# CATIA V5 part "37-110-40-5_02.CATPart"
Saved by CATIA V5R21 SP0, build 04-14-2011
Part number: 37-110-40-5_02
Bounding box of the stored display mesh (mm): x -31 to 5, y 0 to 10.499, z -20 to 20
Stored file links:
  C:\Users\zerma\Pictures\Stage Stomate\37-110-40-5_02.CATPart
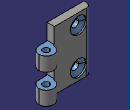
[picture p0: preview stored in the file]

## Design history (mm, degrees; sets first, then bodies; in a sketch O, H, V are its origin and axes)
AxisSystem1: origin (0, 0, 0), X (1, 0, 0), Y (0, 1, 0), Z (0, 0, 1)
Set1
  DatumCurve1 to DatumCurve3
Body1 "37-110-40-5_02" (main body)
  Solid1: solid without history
  Sketch1 on face of Solid1, origin (0, 5, 0), H (-1, 0, 0), V (0, 0, 1)
    circle A1 centre (12.5, 12.5) radius 5.25
    reference projected arc E1 centre (12.5, 12.5) radius 5.25 from (12.5, 17.75) to (12.5, 7.25) ccw from edge [face of Solid1 | face of Solid1]
    circle A2 centre (12.5, -12.5) radius 5.25
    reference projected arc E2 centre (12.5, -12.5) radius 5.25 from (12.5, -7.25) to (12.5, -17.75) ccw from edge [face of Solid1 | face of Solid1]
    coincidence: E1 A1, A2 E2
  Pad1: profile Sketch1, direction (0, -1, 0), up to face of Solid1
  Sketch2 on face of Solid1, origin (-20, 0, 0), H (0, -1, 0), V (0, 0, 1)
    line L1 (-5, 20) -> (0, 20)
    line L2 (0, 20) -> (0, -20)
    line L3 (0, -20) -> (-5, -20)
    line L4 (-5, -20) -> (-5, 20)
    reference projected line E1 (0, 20) -> (-5, 20) from edge [face of Solid1 | face of Solid1]
    reference projected line E2 (-1.6667, -20) -> (0, -20) from edge [face of Solid1 | face of Solid1]
    reference projected line E3 (0, 20) -> (0, -20) from edge [face of Solid1 | face of Solid1]
    reference projected line E4 (-5, 9.306) -> (-5, -9.306) from edge [face of Solid1 | face of Solid1]
    horizontal: L1 H, L3 H
    vertical: L2 V, L4 V
    coincidence: L1 E1, E2 L3, L2 E3, L4 E4
  Pad2: profile Sketch2, direction (-1, 0, 0), length 7, mirrored extent
  Sketch3 on face of Pad2, origin (0, 5, 0), H (-1, 0, 0), V (0, 0, 1)
    circle A1 centre (22.5, 12.4982) radius 0
    circle A2 centre (22.5, -12.5018) radius 2.5
    reference projected circle E1 centre (22.5, -12.5018) radius 2.5 from edge of DatumCurve2
    reference projected circle E2 centre (22.5, -12.5018) radius 2.5 from edge of DatumCurve2
    circle A3 centre (22.5, 12.4982) radius 2.5
    reference projected circle E3 centre (22.5, 12.4982) radius 2.5 from edge of DatumCurve3
    reference projected circle E4 centre (22.5, 12.4982) radius 2.5 from edge of DatumCurve3
    coincidence: A2 E1, E3 A3
    concentricity: A2 E2, E4 A3
  Pocket1: profile Sketch3, direction (0, -1, 0), length 7
  Pad3: profile end face of Pad2, direction along edge [face of Pad2 | face of Pad2], length 4
  Sketch4 on face of Pad3, origin (0, 5, 0), H (-1, 0, 0), V (0, 0, 1)
    circle A1 centre (22.5, 12.4982) radius 5.5
    reference projected circle E1 centre (22.5, 12.4982) radius 2.5 from edge [face of Pad2 | face of Pocket1 from Sketch3.A3]
    circle A2 centre (22.5, -12.5018) radius 5.5
    reference projected circle E2 centre (22.5, -12.5018) radius 2.5 from edge [face of Pad2 | face of Pocket1 from Sketch3.A2]
    radius A1 = 5.5
    radius A2 = 5.5
    concentricity: A1 E1, A2 E2
  Pocket2: profile Sketch4, direction (0, -1, 0), length 1
  Chamfer1: length 3, angle 26.558, on edge [end face of Pocket2 | face of Pocket1 from Sketch3.A2]
  Chamfer2: length 3, angle 26.558, on edge [end face of Pocket2 | face of Pocket1 from Sketch3.A3]
  Fillet1: radius 3.333, on edge [face of Pad3 | end face of Pad3]
  Sketch5 on face of Solid1, origin (0, 0, 10), H (1, 0, 0), V (0, 1, 0)
    line L1 (-6, 30) -> (14, 30)
    line L2 (14, 30) -> (14, 0)
    line L3 (14, 0) -> (-6, 0)
    line L4 (-6, 0) -> (-6, 30)
    reference projected line E1 (-6, 0) -> (-6, 5) from edge [face of Solid1 | face of Pad3]
    reference projected line E2 (-20, 0) -> (-6, 0) from edge [face of Pad3 | face of Pad3]
    horizontal: L1 H, L3 H
    vertical: L2 V, L4 V
    coincidence: L4 E1, L3 E2
  Pocket3: profile Sketch5, direction (0, 0, -1), length 0.5
  Sketch6 on face of Solid1, origin (0, 0, -10), H (1, 0, 0), V (0, 1, 0)
    line L1 (-6, 42.7222) -> (14, 42.7222)
    line L2 (14, 42.7222) -> (14, 0)
    line L3 (14, 0) -> (-6, 0)
    line L4 (-6, 0) -> (-6, 42.7222)
    reference projected line E1 (-6, 0) -> (-6, 5) from edge [face of Pocket3 | face of Pad3]
    reference projected line E2 (-20, 0) -> (-6, 0) from edge [face of Pad3 | face of Pad3]
    horizontal: L1 H, L3 H
    vertical: L2 V, L4 V
    coincidence: L4 E1, L3 E2
  Pocket4: profile Sketch6, direction (0, 0, -1), length 0.5
  Sketch7 on end face of Pocket3, origin (0, 0, 9.5), H (1, 0, 0), V (0, 1, 0)
    circle A1 centre (0, 5.5) radius 2.2
    reference projected arc E1 centre (0, 5.5) radius 2 from (2, 5.5) to (-2, 5.5) ccw from edge [end face of Pocket3 | face of Solid1]
    radius A1 = 2.2
    concentricity: A1 E1
  Pocket5: profile Sketch7, direction (0, 0, -1), up to face of Pad3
